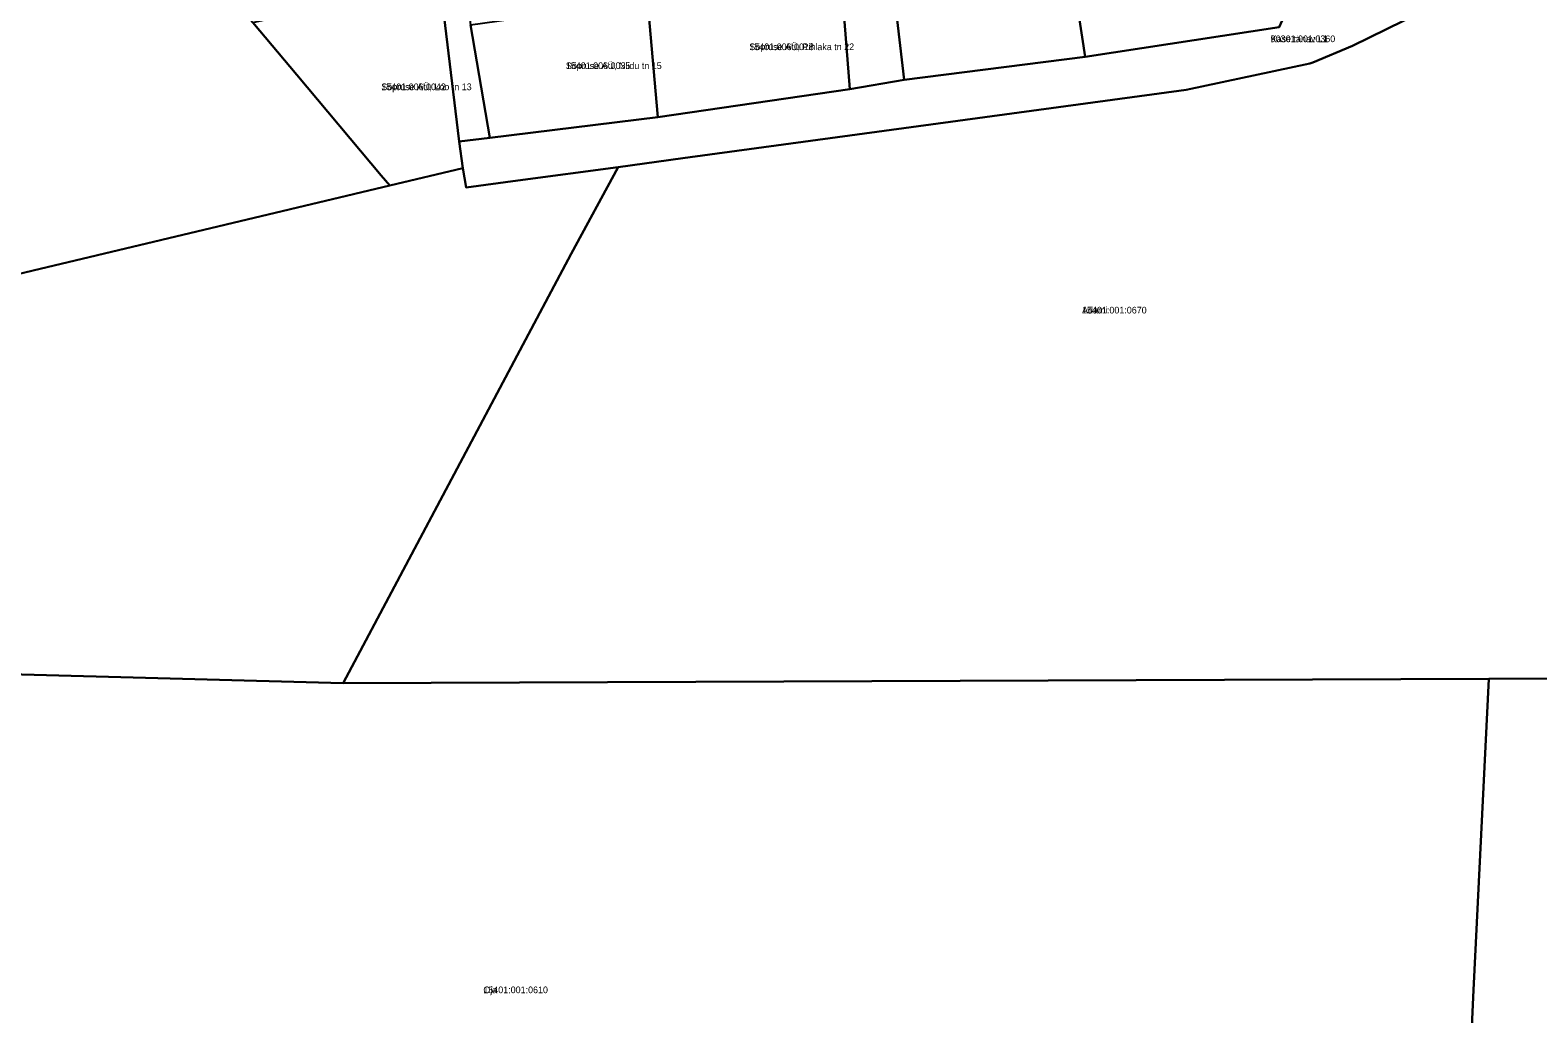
# Model space of a CAD drawing. Extents: x 634518 to 667988, y 6584667 to 6604739.
# Drawn here: x 662955.6 to 663294.1, y 6593025.8 to 6593246.7 of the extents above; entities that cross this region are included whole.
import ezdxf

# ---------------------------------------------------------------- set-up
doc = ezdxf.new("R2010")
doc.units = 0
for name, color, linetype in [('L_AADRESS', 7, 'Continuous'), ('PIIR', 7, 'Continuous'), ('TUNNUS', 7, 'Continuous')]:
    doc.layers.add(name, color=color, linetype=linetype)

msp = doc.modelspace()

# ---------------------------------------------------------------- linework, layer by layer
at = {"layer": 'PIIR'}
for points in [[(663114.37, 6593467.06), (663124.88, 6593474.7), (663126.17, 6593459.9), (663128.72, 6593434.86), (663131.36, 6593410.4), (663134, 6593384.55), (663136.76, 6593360.24), (663139.41, 6593334.94), (663142.15, 6593311.32), (663145.42, 6593286.17), (663148.96, 6593260.03), (663151.82, 6593235.53), (663139.66, 6593233.48), (663137.73, 6593257.26), (663134.09, 6593283.74), (663131.09, 6593308.96), (663128.29, 6593333.98), (663125.76, 6593358.26), (663122.89, 6593383.46), (663120.76, 6593409.28), (663117.61, 6593436.02)], [(663033.46, 6593373.51), (663042.33, 6593382.1), (663041.82, 6593377.78), (663043.11, 6593366.34), (663044.84, 6593348.84), (663047.15, 6593324.41), (663048.38, 6593312.29), (663049.73, 6593299.94), (663052.57, 6593274.58), (663050.91, 6593274.38), (663054.5, 6593247.87), (663058.85, 6593222.49), (663051.92, 6593221.69), (663048, 6593254.65), (663044.64, 6593283.63), (663040.9, 6593312.58), (663037.65, 6593339.37)], [(663051.92, 6593221.69), (663058.85, 6593222.49), (663096.51, 6593227.16), (663139.66, 6593233.48), (663151.82, 6593235.53), (663192.45, 6593240.67), (663236.02, 6593247.4), (663237.33, 6593250.38), (663247.41, 6593256.96), (663298.58, 6593274.43), (663301.52, 6593276.65), (663306, 6593266.08), (663304.39, 6593265.7), (663298.27, 6593264.58), (663290.65, 6593262), (663252.5, 6593243.18), (663243.54, 6593239.44), (663242.91, 6593239.18), (663215.16, 6593233.28), (663102.17, 6593217.97), (663087.61, 6593215.97), (663065.09, 6593212.94), (663053.47, 6593211.36), (663052.77, 6593215.74)], [(663188.82, 6593264.79), (663235.09, 6593271.08), (663237.33, 6593250.38), (663236.02, 6593247.4), (663192.45, 6593240.67)], [(663307.64, 6593259.58), (663314.76, 6593167.62), (663325.51, 6593162.57), (663353.9, 6593149.24), (663341.95, 6593101.12), (663283.08, 6593101.01), (663025.91, 6593100.09), (663077.08, 6593196.44), (663087.61, 6593215.97), (663102.17, 6593217.97), (663215.16, 6593233.28), (663242.91, 6593239.18), (663243.54, 6593239.44), (663252.5, 6593243.18), (663290.65, 6593262), (663298.27, 6593264.58), (663304.39, 6593265.7), (663306, 6593266.08)], [(663148.96, 6593260.03), (663188.82, 6593264.79), (663192.45, 6593240.67), (663151.82, 6593235.53)], [(663094.19, 6593253.44), (663137.73, 6593257.26), (663139.66, 6593233.48), (663096.51, 6593227.16)], [(663005.64, 6593248.42), (663013.31, 6593250.15), (663048, 6593254.65), (663051.92, 6593221.69), (663052.77, 6593215.74), (663036.35, 6593211.79), (663034.4, 6593214.04), (663015.48, 6593236.64)], [(663054.5, 6593247.87), (663094.19, 6593253.44), (663096.51, 6593227.16), (663058.85, 6593222.49)], [(663279.65, 6593031.16), (663283.08, 6593101.01), (663341.95, 6593101.12), (663353.9, 6593149.24), (663366.71, 6593142.29), (663375.75, 6593137.39), (663417.18, 6593140.75), (663417.84, 6593115.56), (663425.58, 6592915.6), (663429.67, 6592795.74), (663392.51, 6592710.65), (663370.6, 6592844.18), (663271.65, 6592852.7), (663276.19, 6592955.77)], [(662837.16, 6593105.16), (663025.91, 6593100.09), (663283.08, 6593101.01), (663279.65, 6593031.16), (663276.19, 6592955.77), (663090.47, 6592965.48), (662833.37, 6592966.86), (662835.14, 6593031.97)]]:
    msp.add_lwpolyline(points, close=True, dxfattribs=at)
for points in [[(662885.24, 6593453.75), (662984.94, 6593349.08), (662986.78, 6593347.15), (662992.27, 6593343.38), (662986.85, 6593335.32), (662964.13, 6593301.91), (662982.9, 6593276.53), (662988.91, 6593268.4), (663005.64, 6593248.42), (663015.48, 6593236.64), (663034.4, 6593214.04), (663036.35, 6593211.79), (662641.65, 6593117.71)], [(662641.65, 6593117.71), (663036.35, 6593211.79), (663052.77, 6593215.74), (663053.47, 6593211.36), (663065.09, 6593212.94), (663087.61, 6593215.97), (663077.08, 6593196.44), (663025.91, 6593100.09), (662837.16, 6593105.16)]]:
    msp.add_lwpolyline(points, dxfattribs=at)

# ---------------------------------------------------------------- texts
at = {"layer": 'L_AADRESS'}
for s, p in [('Sõpruse AÜ, Pihlaka tn 22', (663117.07, 6593242.21)), ('Kase tänav L1', (663234.11, 6593244)), ('Sõpruse AÜ, Niidu tn 15', (663075.88, 6593237.96)), ('Sõpruse AÜ, Loo tn 13', (663034.45, 6593233.22)), ('Adami', (663191.77, 6593183.08)), ('Oja', (663057.36, 6593030.46))]:
    msp.add_text(s, height=1.5, dxfattribs=at).set_placement(p)
at = {"layer": 'TUNNUS'}
for s, p in [('15401:006:0018', (663117.07, 6593242.21)), ('90301:001:0360', (663234.11, 6593244)), ('15401:006:0035', (663075.88, 6593237.96)), ('15401:006:0042', (663034.45, 6593233.22)), ('15401:001:0670', (663191.77, 6593183.08)), ('15401:001:0610', (663057.36, 6593030.46))]:
    msp.add_text(s, height=1.5, dxfattribs=at).set_placement(p)

doc.saveas('drawing.dxf')
